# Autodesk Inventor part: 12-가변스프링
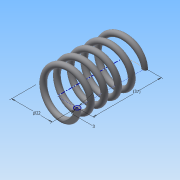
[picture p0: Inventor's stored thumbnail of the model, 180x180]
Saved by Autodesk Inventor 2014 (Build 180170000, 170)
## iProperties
Created: 2015-09
Part Number: 12-가변스프링
Material: 강철, 탄소
Document SubType Name: Modeling
Designer: study
Density: 7.87 g/cm^3
Appearance: 반연마
Mass: 18.9134 g
Surface Area: 32.569 cm^2
Volume: 2.40323 cm^3
Author: study
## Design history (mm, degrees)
sketch "스케치1"
  geometry: L1 (0, 0)-(11, 0); L2 (11, 0)-(11, 28.893); L3 (11, 28.893)-(0, 28.893); L4 (0, 28.893)-(0, 0); C1 r 1.5 at (11, 0)
  constraints: 8 end point, 2 parallel, 1 centre point, 1 coincident, 1 horizontal, 1 perpendicular
  dimensions: "d0" = 3 diameter of C1; "d1" = 22 diameter of L2 L4; "d2" = 28.89259 distance of L1.end L2.end (derived)
feature "코일1" pitch "d3" = 10; turns "d5" = 5; dims "d4" = 28.89259 (= d2), "d6" = 0, angle "d7" = 90 deg, angle "d8" = 90 deg, "d9" = 0, "d10" = 0
node "작업 평면1"
sketch "스케치2"
  geometry: L1 (-12.5, 0)-(-9.5, 0) reference; L2 (-12.5, 0)-(-9.5, 0) reference; 1 further point
  constraints: 2 horizontal alignment
extrude "돌출1" cut sketch "스케치2" stored distance "d12" = 10; taper "d13" = 0 deg
node "작업 평면2"
sketch "스케치3"
  geometry: L1 (-9.5, 0)-(-12.5, 0) reference; 1 further point
  constraints: 1 horizontal alignment
extrude "돌출2" cut sketch "스케치3" stored distance "d15" = 10; taper "d16" = 0 deg
node "솔리드1"
node "절단 모서리 투영1"
node "절단 모서리 투영2"
node "절단 모서리 투영3"
other parameters: "d11" = 0, "d14" = 28.89259 (= d2)
